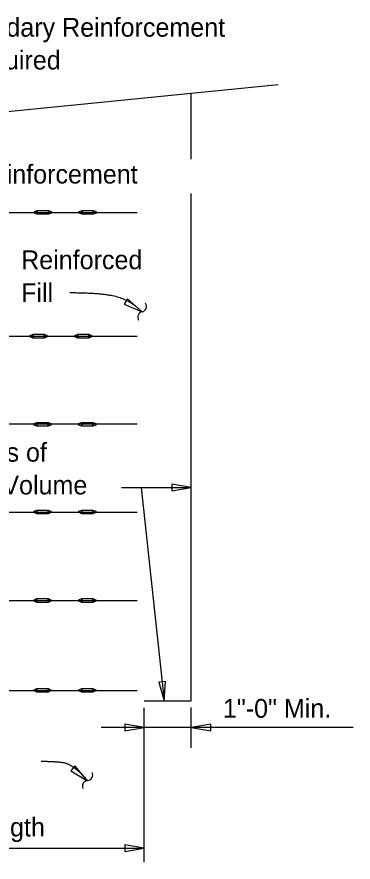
# Model space of a CAD drawing. Extents: x 126777.1 to 126780.68, y 176294.14 to 176295.44.
# Drawn here: x 126779.3418 to 126779.4548, y 176295.0005 to 176295.2841 of the extents above; entities that cross this region are included whole.
import ezdxf

# ---------------------------------------------------------------- set-up
doc = ezdxf.new("R2010")
doc.units = 0
for name, color, linetype in [('AdhocPoint_dp', 7, 'Continuous'), ('Miscellaneous', 7, 'Continuous'), ('TextMisc', 7, 'Continuous')]:
    doc.layers.add(name, color=color, linetype=linetype)

msp = doc.modelspace()

# ---------------------------------------------------------------- linework, layer by layer
at = {"layer": 'AdhocPoint_dp'}
for p, q in [((126779.23956, 176295.24245), (126779.42962, 176295.26141)), ((126779.37694, 176295.12619), (126779.40038, 176295.12619)), ((126779.38356, 176295.12619), (126779.39124, 176295.05457)), ((126779.38456, 176295.00047), (126779.38456, 176295.05224)), ((126779.4004, 176295.03885), (126779.4004, 176295.0524)), ((126779.45477, 176295.04562), (126779.37014, 176295.04562)), ((126779.38456, 176295.04562), (126779.38456, 176295.04562)), ((126779.38456, 176295.04562), (126779.38456, 176295.04562)), ((126779.24097, 176295.00516), (126779.38456, 176295.00516))]:
    msp.add_line(p, q, dxfattribs=at)
for points in [[(126779.38389, 176295.1851), (126779.37897, 176295.18951), (126779.37779, 176295.18764)], [(126779.4004, 176295.12615), (126779.39389, 176295.12725), (126779.39389, 176295.12504)], [(126779.39128, 176295.05453), (126779.39169, 176295.06112), (126779.38949, 176295.06088)], [(126779.38456, 176295.04562), (126779.37806, 176295.04673), (126779.37806, 176295.04452)], [(126779.4004, 176295.04562), (126779.40691, 176295.04452), (126779.40691, 176295.04673)], [(126779.36555, 176295.02776), (126779.36127, 176295.03279), (126779.35986, 176295.0311)], [(126779.38456, 176295.00516), (126779.37806, 176295.00626), (126779.37806, 176295.00405)]]:
    msp.add_lwpolyline(points, close=True, dxfattribs=at)
for centre, start, end in [((126779.38348, 176295.18696), 281.9463, 33.6735), ((126779.38425, 176295.18332), 101.9463, 213.6735), ((126779.3654, 176295.02969), 274.2175, 25.9447), ((126779.36567, 176295.02597), 94.2175, 205.9447)]:
    msp.add_arc(centre, 0.00186, start, end, dxfattribs=at)
for points in [[(126779.35956, 176295.19157), (126779.3701, 176295.19157), (126779.3799, 176295.18908), (126779.38385, 176295.18512)], [(126779.34997, 176295.03431), (126779.35416, 176295.03431), (126779.3605, 176295.03348), (126779.36552, 176295.02781)]]:
    msp.add_open_spline(points, degree=2, dxfattribs=at)
at = {"layer": 'Miscellaneous'}
for p, q in [((126779.4004, 176295.23639), (126779.4004, 176295.25849)), ((126779.4004, 176295.05453), (126779.4004, 176295.22482)), ((126779.24238, 176295.21849), (126779.38217, 176295.21849)), ((126779.24097, 176295.17693), (126779.38217, 176295.17693)), ((126779.24097, 176295.14755), (126779.38217, 176295.14755)), ((126779.24097, 176295.11792), (126779.38217, 176295.11792)), ((126779.24097, 176295.08823), (126779.38217, 176295.08823)), ((126779.24097, 176295.05807), (126779.38217, 176295.05807)), ((126779.38456, 176295.05453), (126779.4004, 176295.05453))]:
    msp.add_line(p, q, dxfattribs=at)
for points in [[(126779.34769, 176295.21875), (126779.34863, 176295.21917), (126779.34863, 176295.21786), (126779.34769, 176295.21828)], [(126779.34863, 176295.21917), (126779.35238, 176295.21917), (126779.35238, 176295.21786), (126779.34863, 176295.21786)], [(126779.35238, 176295.21917), (126779.35331, 176295.21875), (126779.35331, 176295.21828), (126779.35238, 176295.21786)], [(126779.36274, 176295.21875), (126779.36368, 176295.21917), (126779.36368, 176295.21786), (126779.36274, 176295.21828)], [(126779.36368, 176295.21917), (126779.36743, 176295.21917), (126779.36743, 176295.21786), (126779.36368, 176295.21786)], [(126779.36743, 176295.21917), (126779.36837, 176295.21875), (126779.36837, 176295.21828), (126779.36743, 176295.21786)], [(126779.34628, 176295.17714), (126779.34722, 176295.1776), (126779.34722, 176295.17625), (126779.34628, 176295.17672)], [(126779.34722, 176295.1776), (126779.35097, 176295.1776), (126779.35097, 176295.17625), (126779.34722, 176295.17625)], [(126779.35097, 176295.1776), (126779.35191, 176295.17714), (126779.35191, 176295.17672), (126779.35097, 176295.17625)], [(126779.36128, 176295.17714), (126779.36222, 176295.1776), (126779.36222, 176295.17625), (126779.36128, 176295.17672)], [(126779.36222, 176295.1776), (126779.36597, 176295.1776), (126779.36597, 176295.17625), (126779.36222, 176295.17625)], [(126779.36597, 176295.1776), (126779.36691, 176295.17714), (126779.36691, 176295.17672), (126779.36597, 176295.17625)], [(126779.34759, 176295.1476), (126779.34852, 176295.14802), (126779.34852, 176295.14672), (126779.34759, 176295.14714)], [(126779.34852, 176295.14802), (126779.35227, 176295.14802), (126779.35227, 176295.14672), (126779.34852, 176295.14672)], [(126779.35227, 176295.14802), (126779.35321, 176295.1476), (126779.35321, 176295.14714), (126779.35227, 176295.14672)], [(126779.36264, 176295.1476), (126779.36358, 176295.14802), (126779.36358, 176295.14672), (126779.36264, 176295.14714)], [(126779.36358, 176295.14802), (126779.36733, 176295.14802), (126779.36733, 176295.14672), (126779.36358, 176295.14672)], [(126779.36733, 176295.14802), (126779.36826, 176295.1476), (126779.36826, 176295.14714), (126779.36733, 176295.14672)], [(126779.34759, 176295.11818), (126779.34852, 176295.11859), (126779.34852, 176295.11729), (126779.34759, 176295.11776)], [(126779.34852, 176295.11859), (126779.35227, 176295.11859), (126779.35227, 176295.11729), (126779.34852, 176295.11729)], [(126779.35227, 176295.11859), (126779.35321, 176295.11818), (126779.35321, 176295.11776), (126779.35227, 176295.11729)], [(126779.36264, 176295.11818), (126779.36358, 176295.11859), (126779.36358, 176295.11729), (126779.36264, 176295.11776)], [(126779.36358, 176295.11859), (126779.36733, 176295.11859), (126779.36733, 176295.11729), (126779.36358, 176295.11729)], [(126779.36733, 176295.11859), (126779.36826, 176295.11818), (126779.36826, 176295.11776), (126779.36733, 176295.11729)], [(126779.34759, 176295.08844), (126779.34852, 176295.08891), (126779.34852, 176295.08755), (126779.34759, 176295.08802)], [(126779.34852, 176295.08891), (126779.35227, 176295.08891), (126779.35227, 176295.08755), (126779.34852, 176295.08755)], [(126779.35227, 176295.08891), (126779.35321, 176295.08844), (126779.35321, 176295.08802), (126779.35227, 176295.08755)], [(126779.36264, 176295.08844), (126779.36358, 176295.08891), (126779.36358, 176295.08755), (126779.36264, 176295.08802)], [(126779.36358, 176295.08891), (126779.36733, 176295.08891), (126779.36733, 176295.08755), (126779.36358, 176295.08755)], [(126779.36733, 176295.08891), (126779.36826, 176295.08844), (126779.36826, 176295.08802), (126779.36733, 176295.08755)], [(126779.34759, 176295.05833), (126779.34852, 176295.05875), (126779.34852, 176295.05745), (126779.34759, 176295.05792)], [(126779.34852, 176295.05875), (126779.35227, 176295.05875), (126779.35227, 176295.05745), (126779.34852, 176295.05745)], [(126779.35227, 176295.05875), (126779.35321, 176295.05833), (126779.35321, 176295.05792), (126779.35227, 176295.05745)], [(126779.36264, 176295.05833), (126779.36358, 176295.05875), (126779.36358, 176295.05745), (126779.36264, 176295.05792)], [(126779.36358, 176295.05875), (126779.36733, 176295.05875), (126779.36733, 176295.05745), (126779.36358, 176295.05745)], [(126779.36733, 176295.05875), (126779.36826, 176295.05833), (126779.36826, 176295.05792), (126779.36733, 176295.05745)]]:
    msp.add_lwpolyline(points, close=True, dxfattribs=at)

# ---------------------------------------------------------------- texts
at = {"layer": 'TextMisc'}
for s, p in [('Secondary Reinforcement', (126779.31436, 176295.27746)), ('as required', (126779.31436, 176295.26646)), ('Primary Reinforcement', (126779.29623, 176295.22818)), ('Reinforced ', (126779.34321, 176295.19943)), ('Fill', (126779.34321, 176295.18843)), ('Limits of ', (126779.3205, 176295.13485)), ('Soil Volume', (126779.3205, 176295.12385)), ('1"-0" Min.', (126779.41102, 176295.04891)), ('Soil Reinforcement Length', (126779.25192, 176295.00906))]:
    msp.add_text(s, height=0.0063, dxfattribs=at).set_placement(p)

doc.saveas('drawing.dxf')
